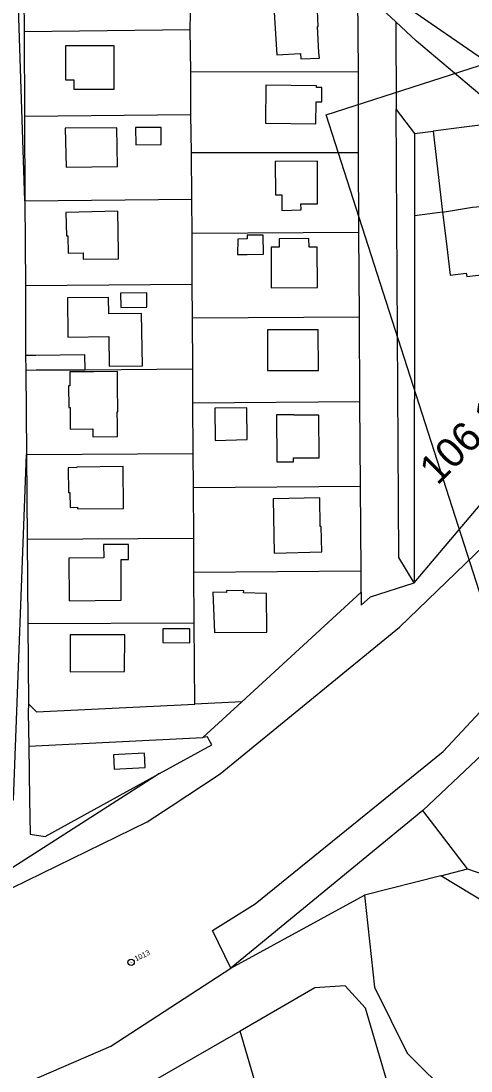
# Model space of a CAD drawing. Extents: x -758836 to -757729, y -1175316 to -1174366.
# Drawn here: x -758589.7 to -758483.3, y -1175013.3 to -1174765.3 of the extents above; entities that cross this region are included whole.
import ezdxf

# ---------------------------------------------------------------- set-up
doc = ezdxf.new("R2010")
doc.units = 0
for name, color, linetype in [('_NOR-pomocná', 7, 'Continuous'), ('Hranice parcel', 7, 'Continuous'), ('Vrstva 63', 7, 'Continuous'), ('Vrstva 7', 7, 'Continuous')]:
    doc.layers.add(name, color=color, linetype=linetype)

# ---------------------------------------------------------------- blocks, each defined once
blk = doc.blocks.new('C015_1')
at = {"layer": 'Vrstva 63'}
blk.add_line((-0.05, 0), (0.05, 0), dxfattribs=at)
blk.add_circle((0, 0), 0.756, dxfattribs=at)

msp = doc.modelspace()

# ---------------------------------------------------------------- linework, layer by layer
at = {"layer": '_NOR-pomocná'}
msp.add_lwpolyline([(-758517.54, -1174787.42), (-758417.59, -1174755.22), (-758372.07, -1174896.57), (-758472.01, -1174928.76)], close=True, dxfattribs=at)
at = {"layer": 'Hranice parcel'}
for p, q in [((-758588.72, -1174807.72), (-758591.88, -1174711.27)), ((-758589.01, -1174747.74), (-758588.92, -1174767.73)), ((-758549.63, -1174767.27), (-758549.49, -1174757.19)), ((-758509.88, -1174777.17), (-758510.04, -1174757.06)), ((-758501.06, -1174765.48), (-758510.04, -1174757.06)), ((-758588.92, -1174767.73), (-758549.63, -1174767.27)), ((-758549.52, -1174777.23), (-758549.63, -1174767.27)), ((-758501.06, -1174765.48), (-758500.94, -1174786.18)), ((-758588.92, -1174767.73), (-758588.82, -1174787.73)), ((-758549.52, -1174777.23), (-758509.88, -1174777.17)), ((-758549.49, -1174787.31), (-758549.52, -1174777.23)), ((-758509.84, -1174796.28), (-758509.88, -1174777.17)), ((-758500.94, -1174786.18), (-758496.67, -1174791.83)), ((-758588.82, -1174787.73), (-758549.49, -1174787.31)), ((-758588.82, -1174787.73), (-758588.72, -1174807.72)), ((-758549.33, -1174796.34), (-758549.49, -1174787.31)), ((-758496.67, -1174791.83), (-758492.23, -1174791.3)), ((-758496.67, -1174791.83), (-758496.67, -1174811.24)), ((-758549.33, -1174796.34), (-758509.84, -1174796.28)), ((-758549.24, -1174807.35), (-758549.33, -1174796.34)), ((-758509.77, -1174815.13), (-758509.84, -1174796.28)), ((-758588.72, -1174807.72), (-758549.24, -1174807.35)), ((-758588.72, -1174807.72), (-758588.63, -1174827.72)), ((-758549.18, -1174815.36), (-758549.24, -1174807.35)), ((-758496.67, -1174811.24), (-758496.7, -1174897.94)), ((-758489.99, -1174810.38), (-758496.67, -1174811.24)), ((-758549.18, -1174815.36), (-758509.77, -1174815.13)), ((-758549.16, -1174827.39), (-758549.18, -1174815.36)), ((-758509.65, -1174835.13), (-758509.77, -1174815.13)), ((-758588.63, -1174827.72), (-758549.16, -1174827.39)), ((-758588.63, -1174827.72), (-758588.56, -1174844.26)), ((-758549.11, -1174835.39), (-758549.16, -1174827.39)), ((-758549.11, -1174835.39), (-758509.65, -1174835.13)), ((-758549.04, -1174847.41), (-758549.11, -1174835.39)), ((-758509.53, -1174855.14), (-758509.65, -1174835.13)), ((-758574.52, -1174847.62), (-758574.55, -1174844.12)), ((-758588.56, -1174844.26), (-758588.53, -1174847.71)), ((-758588.53, -1174847.71), (-758588.38, -1174867.67)), ((-758574.52, -1174847.62), (-758549.04, -1174847.41)), ((-758549, -1174855.43), (-758549.04, -1174847.41)), ((-758549, -1174855.43), (-758509.53, -1174855.14)), ((-758548.93, -1174867.42), (-758549, -1174855.43)), ((-758509.4, -1174875.14), (-758509.53, -1174855.14)), ((-758496.7, -1174897.94), (-758462.28, -1174857.27)), ((-758588.38, -1174867.67), (-758548.93, -1174867.42)), ((-758588.38, -1174867.67), (-758588.22, -1174887.63)), ((-758548.88, -1174875.41), (-758548.93, -1174867.42)), ((-758548.88, -1174875.41), (-758509.4, -1174875.14)), ((-758548.81, -1174887.41), (-758548.88, -1174875.41)), ((-758509.28, -1174895.15), (-758509.4, -1174875.14)), ((-758588.22, -1174887.63), (-758548.81, -1174887.41)), ((-758588.22, -1174887.63), (-758588.06, -1174907.59)), ((-758548.77, -1174895.41), (-758548.81, -1174887.41)), ((-758548.77, -1174895.41), (-758509.28, -1174895.15)), ((-758548.7, -1174907.41), (-758548.77, -1174895.41)), ((-758509.25, -1174900.15), (-758509.28, -1174895.15)), ((-758537.48, -1174926.06), (-758509.25, -1174900.15)), ((-758588.06, -1174907.59), (-758548.7, -1174907.41)), ((-758588.06, -1174907.59), (-758587.91, -1174926.56)), ((-758548.59, -1174926.64), (-758548.7, -1174907.41)), ((-758537.48, -1174926.06), (-758548.59, -1174926.64)), ((-758546.66, -1174934.51), (-758537.48, -1174926.06)), ((-758587.83, -1174936.54), (-758546.66, -1174934.51)), ((-758494.7, -1174951.75), (-758540.08, -1174988.98)), ((-758484.1, -1174965.51), (-758494.7, -1174951.75)), ((-758490.43, -1174967.13), (-758484.1, -1174965.51)), ((-758490.43, -1174967.13), (-758508.47, -1174971.76)), ((-758479.07, -1174974.04), (-758490.43, -1174967.13)), ((-758540.08, -1174988.98), (-758508.47, -1174971.76)), ((-758540.08, -1174988.98), (-758544.35, -1174980.07)), ((-758528.34, -1175036.07), (-758537.87, -1175003.83))]:
    msp.add_line(p, q, dxfattribs=at)
for points in [[(-758466.28, -1174780.52), (-758466.54, -1174782.53), (-758466.7, -1174783.79), (-758499, -1174761.63), (-758510.58, -1174750.09), (-758507.04, -1174746.79), (-758503.32, -1174743.41)], [(-758529.99, -1174760.86), (-758529.84, -1174763.25), (-758529.19, -1174773.23), (-758523.57, -1174772.91), (-758523.49, -1174774.21), (-758519.13, -1174774.01), (-758519.21, -1174772.67), (-758519.57, -1174766.55), (-758519.37, -1174766.54), (-758519.6, -1174762.74), (-758520.82, -1174762.81), (-758521.03, -1174760.42), (-758529.99, -1174760.86)], [(-758473.72, -1174788.92), (-758496.19, -1174770.04), (-758501.06, -1174765.48)], [(-758567.61, -1174781.34), (-758567.62, -1174771.12), (-758577.21, -1174771.11), (-758579.17, -1174771.11), (-758579.16, -1174779.12), (-758577.2, -1174779.12), (-758577.2, -1174781.36), (-758567.61, -1174781.34)], [(-758519.83, -1174780.55), (-758531.78, -1174780.43), (-758531.87, -1174789.39), (-758519.92, -1174789.51), (-758519.87, -1174784.37), (-758518.55, -1174784.38), (-758518.52, -1174781), (-758519.83, -1174780.99), (-758519.83, -1174780.55)], [(-758496.7, -1174897.94), (-758500.3, -1174891.98), (-758500.94, -1174786.18)], [(-758473.72, -1174788.92), (-758479.82, -1174789.69), (-758484.93, -1174790.34), (-758492.23, -1174791.3)], [(-758579.18, -1174790.6), (-758578.99, -1174799.77), (-758566.88, -1174799.63), (-758566.99, -1174790.49), (-758579.18, -1174790.6)], [(-758562.53, -1174794.48), (-758556.49, -1174794.42), (-758556.53, -1174790.39), (-758562.57, -1174790.45), (-758562.53, -1174794.48)], [(-758492.23, -1174791.3), (-758490.61, -1174804.99), (-758489.99, -1174810.38)], [(-758528.02, -1174806.28), (-758527.98, -1174809.99), (-758523.43, -1174809.9), (-758523.5, -1174808.47), (-758519.54, -1174808.45), (-758519.57, -1174798.39), (-758529.54, -1174798.44), (-758529.5, -1174806.29), (-758528.02, -1174806.28)], [(-758489.99, -1174810.38), (-758482.89, -1174809.27), (-758477.43, -1174808.72)], [(-758578.93, -1174816.04), (-758578.62, -1174816.03), (-758578.53, -1174820.11), (-758574.99, -1174820.04), (-758574.97, -1174821.55), (-758566.57, -1174821.41), (-758566.6, -1174819.87), (-758566.8, -1174810.19), (-758579.05, -1174810.47), (-758578.93, -1174816.04)], [(-758489.99, -1174810.38), (-758489.17, -1174817.3), (-758488.24, -1174825.29)], [(-758538.44, -1174820.41), (-758536.16, -1174820.39), (-758532.36, -1174820.36), (-758532.39, -1174815.82), (-758536.19, -1174815.86), (-758536.18, -1174816.73), (-758538.42, -1174816.75), (-758538.44, -1174820.41)], [(-758521.56, -1174818.64), (-758521.6, -1174816.66), (-758528.59, -1174816.68), (-758528.59, -1174818.65), (-758530.53, -1174818.65), (-758530.51, -1174828.26), (-758519.54, -1174828.24), (-758519.62, -1174818.64), (-758521.56, -1174818.64)], [(-758488.24, -1174825.29), (-758484.39, -1174824.82), (-758484.3, -1174825.64), (-758480.16, -1174825.17), (-758480.23, -1174824.63), (-758469.8, -1174823.45), (-758470.75, -1174815.07)], [(-758561.17, -1174834.32), (-758568.91, -1174834.39), (-758568.94, -1174830.58), (-758578.66, -1174830.62), (-758578.61, -1174839.93), (-758568.86, -1174839.81), (-758568.8, -1174846.79), (-758560.97, -1174846.72), (-758561.17, -1174834.32)], [(-758566.07, -1174832.89), (-758559.87, -1174832.87), (-758559.92, -1174829.44), (-758566.12, -1174829.53), (-758566.07, -1174832.89)], [(-758531.42, -1174838.19), (-758531.4, -1174847.78), (-758519.29, -1174847.81), (-758519.42, -1174838.17), (-758531.42, -1174838.19)], [(-758574.55, -1174844.12), (-758586.13, -1174844.24), (-758588.56, -1174844.26)], [(-758588.53, -1174847.71), (-758586.06, -1174847.69), (-758579.05, -1174847.64), (-758574.52, -1174847.62)], [(-758566.87, -1174860.58), (-758566.9, -1174857.55), (-758566.75, -1174857.55), (-758566.81, -1174851.24), (-758566.85, -1174848.02), (-758572.42, -1174848.09), (-758578.15, -1174848.13), (-758578.12, -1174851.46), (-758578.46, -1174851.46), (-758578.38, -1174856.53), (-758578.07, -1174856.53), (-758578.03, -1174861.67), (-758572.66, -1174861.62), (-758572.64, -1174863.46), (-758566.85, -1174863.41), (-758566.87, -1174860.58)], [(-758536.28, -1174856.64), (-758543.84, -1174856.72), (-758543.79, -1174864.36), (-758536.22, -1174864.13), (-758536.28, -1174856.64)], [(-758525.18, -1174858.39), (-758525.18, -1174858.27), (-758529.28, -1174858.28), (-758529.19, -1174869.41), (-758525.23, -1174869.4), (-758525.23, -1174868.47), (-758519.15, -1174868.47), (-758519.26, -1174858.38), (-758525.18, -1174858.39)], [(-758749.71, -1175018.36), (-758683.75, -1175000), (-758648.73, -1174990.25), (-758595.39, -1174971.76), (-758559.83, -1174954.39), (-758554.18, -1174950.69), (-758542.58, -1174943.09), (-758500.14, -1174908.44), (-758460.25, -1174869.94), (-758457.56, -1174867.46)], [(-758598.15, -1174949.55), (-758591.43, -1174949.22), (-758588.38, -1174867.67)], [(-758576.49, -1174870.75), (-758578.49, -1174870.79), (-758578.39, -1174876.66), (-758578.09, -1174876.66), (-758578.02, -1174880.14), (-758576.31, -1174880.11), (-758576.3, -1174880.49), (-758565.41, -1174880.4), (-758565.54, -1174870.48), (-758576.49, -1174870.61), (-758576.49, -1174870.75)], [(-758518.9, -1174884.67), (-758519.02, -1174877.9), (-758530.07, -1174878.13), (-758529.83, -1174890.98), (-758518.54, -1174890.66), (-758518.66, -1174884.67), (-758518.9, -1174884.67)], [(-758565.97, -1174892.44), (-758564.21, -1174892.45), (-758564.22, -1174888.94), (-758570.14, -1174888.94), (-758570.11, -1174892.08), (-758578.34, -1174892.15), (-758578.24, -1174902.2), (-758566.01, -1174902.08), (-758565.97, -1174892.44)], [(-758509.25, -1174900.15), (-758509.23, -1174903.24), (-758507.04, -1174901.3), (-758496.7, -1174897.94)], [(-758544.33, -1174900.19), (-758543.94, -1174909.68), (-758531.57, -1174909.63), (-758531.61, -1174900.48), (-758537.02, -1174900.36), (-758537.01, -1174899.88), (-758541.07, -1174899.78), (-758541.08, -1174900.26), (-758544.33, -1174900.19)], [(-758578.05, -1174910.27), (-758578.01, -1174919), (-758565.21, -1174918.94), (-758565.08, -1174910.27), (-758578.05, -1174910.27)], [(-758556.13, -1174908.84), (-758556.15, -1174912.09), (-758549.76, -1174912.13), (-758549.74, -1174908.83), (-758556.13, -1174908.84)], [(-758544.35, -1174980.07), (-758534.26, -1174973.76), (-758489.89, -1174937.8), (-758465.75, -1174911.99), (-758459.45, -1174912.25)], [(-758456.16, -1174915.41), (-758473.44, -1174931.75), (-758494.7, -1174951.75)], [(-758587.91, -1174926.56), (-758587.96, -1174928.54), (-758587.83, -1174936.54)], [(-758587.91, -1174926.56), (-758585.96, -1174928.44), (-758548.59, -1174926.64)], [(-758556.89, -1174943.02), (-758544.56, -1174936.26), (-758545.16, -1174935.1), (-758545.54, -1174934.37), (-758546.66, -1174934.51)], [(-758587.83, -1174936.54), (-758587.62, -1174949.03), (-758587.48, -1174957.31), (-758583.93, -1174957.84), (-758556.89, -1174943.02)], [(-758566.32, -1174941.89), (-758560.29, -1174941.57), (-758560.46, -1174938.22), (-758566.5, -1174938.54), (-758567.8, -1174938.61), (-758567.66, -1174941.96), (-758566.32, -1174941.89)], [(-758556.89, -1174943.02), (-758591.6, -1174965.21), (-758598.85, -1174965.89)], [(-758484.1, -1174965.51), (-758456.91, -1174975), (-758446.51, -1174978.25), (-758434.83, -1174979.65), (-758424.43, -1174975.65), (-758423.87, -1174972.53), (-758420.99, -1174956.58)], [(-758508.47, -1174971.76), (-758506.08, -1174993.49), (-758498.33, -1175009.04), (-758477.28, -1175030)], [(-758633.16, -1175038.79), (-758629.62, -1175031.39), (-758600.05, -1175021.05), (-758568.41, -1175007.42), (-758540.08, -1174988.98)], [(-758501.21, -1175022.31), (-758508.18, -1174998.44), (-758513.01, -1174993.13), (-758520.17, -1174993.64), (-758537.87, -1175003.83)], [(-758537.87, -1175003.83), (-758558.93, -1175015.96), (-758562.5, -1175020.07), (-758562.75, -1175025.5), (-758555.54, -1175049.88)]]:
    msp.add_lwpolyline(points, dxfattribs=at)

# ---------------------------------------------------------------- block references
at = {"layer": 'Vrstva 63', "rotation": 26.419936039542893}
msp.add_blockref('C015_1', (-758563.62, -1174987.6), dxfattribs=at)

# ---------------------------------------------------------------- texts
at = {"layer": 'Vrstva 63'}
msp.add_text('1013', height=1.25, rotation=26.4199, dxfattribs=at).set_placement((-758562.45, -1174987.41))
at = {"layer": 'Vrstva 7'}
msp.add_text('106,1', height=6.972, rotation=44.9683, dxfattribs=at).set_placement((-758491.2, -1174875.13))

doc.saveas('drawing.dxf')
